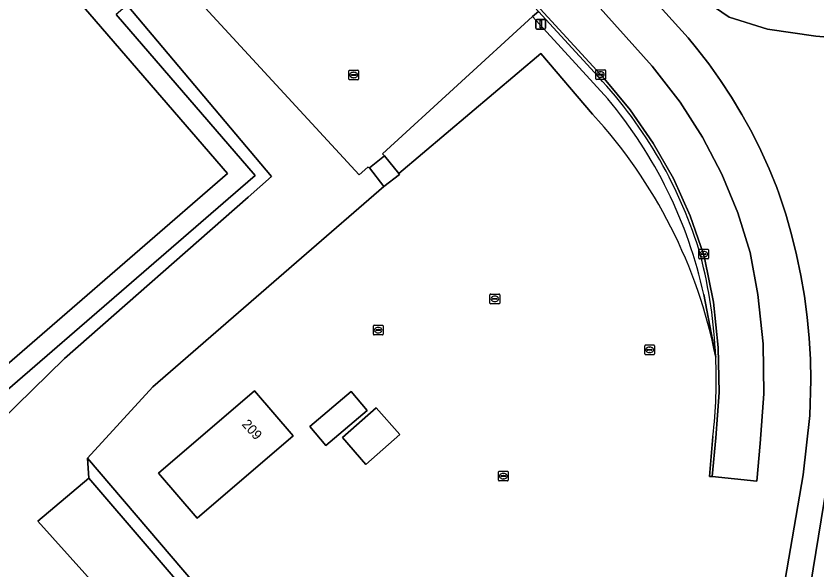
# Model space of a CAD drawing. Extents: x 156061 to 157804, y 383437 to 385640.
# Drawn here: x 157609.8 to 157692.3, y 383598 to 383655.1 of the extents above; entities that cross this region are included whole.
import ezdxf

# ---------------------------------------------------------------- set-up
doc = ezdxf.new("R2010")
doc.units = 0
for name, color, linetype in [('IMGEO_Erf', 7, 'Continuous'), ('IMGEO_Fietspad_gesloten', 7, 'Continuous'), ('IMGEO_Grasland_overig', 7, 'Continuous'), ('IMGEO_Groenvoorziening', 7, 'Continuous'), ('IMGEO_Hek', 7, 'Continuous'), ('IMGEO_Kolk', 7, 'Continuous'), ('IMGEO_Lichtmast', 7, 'Continuous'), ('IMGEO_Meer_plas_ven_vijver', 7, 'Continuous'), ('IMGEO_Oever', 7, 'Continuous'), ('IMGEO_Pand', 7, 'Continuous'), ('IMGEO_Pand_nummerreeks', 7, 'Continuous'), ('IMGEO_Rijbaan_lokaal_gesloten', 7, 'Continuous'), ('IMGEO_Rijbaan_lokaal_open', 7, 'Continuous'), ('IMGEO_Voetpad_gesloten', 7, 'Continuous')]:
    doc.layers.add(name, color=color, linetype=linetype)

msp = doc.modelspace()

# ---------------------------------------------------------------- linework, layer by layer
at = {"layer": 'IMGEO_Erf'}
for points in [[(157663.038, 383655.013), (157663.63, 383655.554), (157652.735, 383667.414), (157649.055, 383671.421), (157642.073, 383679.016), (157636.298, 383685.833), (157635.64, 383685.18), (157622.846, 383673.301), (157622.498, 383673.653), (157617.28, 383668.944), (157624.23, 383661.417), (157624.003, 383661.197), (157625.333, 383659.711), (157625.613, 383659.933), (157645.162, 383638.719), (157646.075, 383639.53), (157646.224, 383639.429), (157647.765, 383640.669), (157647.565, 383640.888)], [(157628.488, 383603.368), (157624.511, 383607.993), (157634.384, 383616.48), (157638.361, 383611.855)], [(157641.73, 383610.838), (157640.071, 383612.794), (157644.334, 383616.41), (157645.994, 383614.453)], [(157645.865, 383608.915), (157643.438, 383611.664), (157646.918, 383614.736), (157649.345, 383611.987)]]:
    msp.add_lwpolyline(points, close=True, dxfattribs=at)
for points in [[(157592.743, 383683.81), (157631.604, 383638.864), (157604.478, 383615.391), (157603.332, 383614.398), (157595.061, 383607.241), (157596.405, 383605.765), (157632.931, 383637.35), (157634.437, 383638.653), (157620.132, 383655.218)], [(157684.771, 383572.107), (157690.917, 383607.847), (157691.599, 383613.955), (157691.7, 383617.579), (157691.654, 383619.746), (157691.528, 383621.909), (157691.322, 383624.067), (157691.036, 383626.215), (157690.672, 383628.351), (157690.228, 383630.473), (157689.707, 383632.577), (157689.109, 383634.66), (157688.434, 383636.719), (157688.181, 383637.431), (157687.395, 383639.355), (157686.535, 383641.247), (157685.604, 383643.105), (157684.601, 383644.926), (157683.529, 383646.707), (157682.39, 383648.445), (157681.184, 383650.138), (157679.914, 383651.783), (157679.054, 383652.828), (157668.815, 383664.162)], [(157668.795, 383657.275), (157675.344, 383649.915), (157675.598, 383649.618), (157678.228, 383646.221), (157680.544, 383642.603), (157682.528, 383638.793), (157684.163, 383634.821), (157685.437, 383630.719), (157686.252, 383626.409), (157686.782, 383621.311), (157686.856, 383616.186), (157686.471, 383611.075), (157686.145, 383607.174), (157681.542, 383607.66), (157681.251, 383607.669), (157681.612, 383611.77)], [(157669.22, 383644.961), (157663.882, 383651.218), (157649.251, 383638.856), (157649.329, 383638.753), (157647.699, 383637.528), (157639.22, 383630.176), (157623.911, 383616.901), (157617.189, 383609.565), (157665.287, 383553.229)]]:
    msp.add_lwpolyline(points, dxfattribs=at)
for centre, radius, start, end in [((157631.14, 383609.93), 51.742, 11.18031, 42.61163), ((157630.359, 383617.673), 51.592, 353.42979, 2.54375)]:
    msp.add_arc(centre, radius, start, end, dxfattribs=at)
at = {"layer": 'IMGEO_Fietspad_gesloten'}
msp.add_lwpolyline([(157677.351, 383659.207), (157680.92, 383656.58), (157683.3, 383654.951), (157687.249, 383653.73), (157692.2, 383653.007), (157695.992, 383652.677), (157702.093, 383652.679)], dxfattribs=at)
at = {"layer": 'IMGEO_Grasland_overig'}
msp.add_lwpolyline([(157665.287, 383553.229), (157617.189, 383609.565), (157617.318, 383607.508), (157666.014, 383550.759)], dxfattribs=at)
at = {"layer": 'IMGEO_Groenvoorziening'}
for points in [[(157668.815, 383664.162), (157679.054, 383652.828), (157679.914, 383651.783), (157681.184, 383650.138), (157682.39, 383648.445), (157683.529, 383646.707), (157684.601, 383644.926), (157685.604, 383643.105), (157686.535, 383641.247), (157687.395, 383639.355), (157688.181, 383637.431), (157688.434, 383636.719), (157689.109, 383634.66), (157689.707, 383632.577), (157690.228, 383630.473), (157690.672, 383628.351), (157691.036, 383626.215), (157691.322, 383624.067), (157691.528, 383621.909), (157691.654, 383619.746), (157691.7, 383617.579), (157691.599, 383613.955), (157690.917, 383607.847), (157684.771, 383572.107)], [(157702.093, 383652.679), (157695.992, 383652.677), (157692.2, 383653.007), (157687.249, 383653.73), (157683.3, 383654.951), (157680.92, 383656.58), (157677.351, 383659.207)], [(157669.795, 383648.842), (157663.63, 383655.554), (157663.038, 383655.013), (157670.77, 383646.55)], [(157670.77, 383646.55), (157663.038, 383655.013), (157647.565, 383640.888), (157647.765, 383640.669), (157649.251, 383638.856), (157663.882, 383651.218), (157669.22, 383644.961)], [(157681.9, 383619.963), (157680.668, 383626.41)], [(157680.668, 383626.41), (157681.9, 383619.963)], [(157689.63, 383522.84), (157689.875, 383524.141), (157686.145, 383524.416), (157685.129, 383524.064), (157683.797, 383523.916), (157682.677, 383524.301), (157681.923, 383525.009), (157681.65, 383525.865), (157681.656, 383527.801), (157682.768, 383535.446), (157685.102, 383556.062), (157686.447, 383563.344), (157687.967, 383573.008), (157691.921, 383598.148), (157695.746, 383621.484)], [(157666.014, 383550.759), (157617.318, 383607.508), (157612.047, 383603.052), (157630.214, 383582.846)]]:
    msp.add_lwpolyline(points, dxfattribs=at)
for points in [[(157617.318, 383607.508), (157617.189, 383609.565), (157623.911, 383616.901), (157639.22, 383630.176), (157647.699, 383637.528), (157646.224, 383639.429), (157646.075, 383639.53), (157645.162, 383638.719), (157625.613, 383659.933), (157625.333, 383659.711), (157621.256, 383656.181), (157636.145, 383638.565), (157633.728, 383636.44), (157614.798, 383619.797), (157598.3, 383603.675), (157604.166, 383597.049), (157613.461, 383586.57), (157620.486, 383578.692), (157622.825, 383576.06), (157630.214, 383582.846), (157612.047, 383603.052)], [(157596.405, 383605.765), (157598.042, 383603.967), (157598.3, 383603.675), (157614.798, 383619.797), (157633.728, 383636.44), (157636.145, 383638.565), (157621.256, 383656.181), (157620.132, 383655.218), (157634.437, 383638.653), (157632.931, 383637.35)]]:
    msp.add_lwpolyline(points, close=True, dxfattribs=at)
for centre, radius, start, end in [((157635.883, 383617.185), 46.391, 16.60587, 43.03067), ((157634.734, 383616.337), 47.026, 12.36822, 39.97631), ((157634.734, 383616.337), 47.026, 12.36822, 39.97631), ((157631.14, 383609.93), 51.742, 11.18031, 42.61163), ((157630.586, 383617.681), 51.364, 2.54655, 14.38663)]:
    msp.add_arc(centre, radius, start, end, dxfattribs=at)
at = {"layer": 'IMGEO_Hek'}
for points in [[(157679.054, 383652.828), (157668.815, 383664.162), (157667.614, 383665.197)], [(157688.181, 383637.431), (157687.395, 383639.355), (157686.535, 383641.247), (157685.604, 383643.105), (157684.601, 383644.926), (157683.529, 383646.707), (157682.39, 383648.445), (157681.184, 383650.138), (157679.914, 383651.783), (157679.054, 383652.828)], [(157691.7, 383617.579), (157691.654, 383619.746), (157691.528, 383621.909), (157691.322, 383624.067), (157691.036, 383626.215), (157690.672, 383628.351), (157690.228, 383630.473), (157689.707, 383632.577), (157689.109, 383634.66), (157688.434, 383636.719), (157688.181, 383637.431)], [(157690.917, 383607.847), (157691.599, 383613.955), (157691.7, 383617.579)], [(157684.771, 383572.107), (157690.917, 383607.847)]]:
    msp.add_lwpolyline(points, dxfattribs=at)
at = {"layer": 'IMGEO_Kolk'}
for p, q in [((157644.177, 383649.505), (157645.029, 383649.505)), ((157669.534, 383648.618), (157669.534, 383649.47)), ((157669.609, 383649.544), (157670.461, 383649.544)), ((157670.535, 383649.47), (157670.535, 383648.618)), ((157644.102, 383648.579), (157644.102, 383649.431)), ((157644.361, 383648.999), (157644.361, 383649.011)), ((157644.799, 383648.962), (157644.401, 383648.962)), ((157644.404, 383649.048), (157644.802, 383649.048)), ((157644.613, 383648.725), (157644.588, 383648.725)), ((157644.59, 383649.285), (157644.615, 383649.285)), ((157644.845, 383649.011), (157644.845, 383648.999)), ((157645.103, 383649.431), (157645.103, 383648.579)), ((157669.793, 383649.038), (157669.793, 383649.05)), ((157670.231, 383649.001), (157669.833, 383649.001)), ((157669.836, 383649.087), (157670.234, 383649.087)), ((157670.045, 383648.764), (157670.02, 383648.764)), ((157670.022, 383649.324), (157670.047, 383649.324)), ((157670.277, 383649.05), (157670.277, 383649.038)), ((157645.029, 383648.505), (157644.177, 383648.505)), ((157670.461, 383648.544), (157669.609, 383648.544)), ((157680.154, 383630.134), (157680.154, 383630.986)), ((157680.229, 383631.06), (157681.081, 383631.06)), ((157680.413, 383630.554), (157680.413, 383630.566)), ((157680.851, 383630.517), (157680.453, 383630.517)), ((157680.456, 383630.603), (157680.854, 383630.603)), ((157680.642, 383630.84), (157680.667, 383630.84)), ((157680.897, 383630.566), (157680.897, 383630.554)), ((157681.155, 383630.986), (157681.155, 383630.134)), ((157681.081, 383630.06), (157680.229, 383630.06)), ((157680.665, 383630.28), (157680.64, 383630.28)), ((157658.644, 383625.524), (157658.644, 383626.376)), ((157658.719, 383626.45), (157659.571, 383626.45)), ((157659.645, 383626.376), (157659.645, 383625.524)), ((157658.903, 383625.944), (157658.903, 383625.956)), ((157659.341, 383625.907), (157658.943, 383625.907)), ((157658.946, 383625.993), (157659.344, 383625.993)), ((157659.155, 383625.67), (157659.13, 383625.67)), ((157659.132, 383626.23), (157659.157, 383626.23)), ((157659.387, 383625.956), (157659.387, 383625.944)), ((157659.571, 383625.45), (157658.719, 383625.45)), ((157646.629, 383622.314), (157646.629, 383623.166)), ((157646.704, 383623.24), (157647.556, 383623.24)), ((157647.63, 383623.166), (157647.63, 383622.314)), ((157647.556, 383622.24), (157646.704, 383622.24)), ((157646.888, 383622.734), (157646.888, 383622.746)), ((157647.326, 383622.697), (157646.928, 383622.697)), ((157646.931, 383622.783), (157647.329, 383622.783)), ((157647.14, 383622.46), (157647.115, 383622.46)), ((157647.117, 383623.02), (157647.142, 383623.02)), ((157647.372, 383622.746), (157647.372, 383622.734)), ((157674.591, 383620.278), (157674.591, 383621.13)), ((157674.666, 383621.204), (157675.518, 383621.204)), ((157674.85, 383620.698), (157674.85, 383620.71)), ((157675.288, 383620.661), (157674.89, 383620.661)), ((157674.893, 383620.747), (157675.291, 383620.747)), ((157675.079, 383620.984), (157675.104, 383620.984)), ((157675.334, 383620.71), (157675.334, 383620.698)), ((157675.592, 383621.13), (157675.592, 383620.278)), ((157675.518, 383620.204), (157674.666, 383620.204)), ((157675.102, 383620.424), (157675.077, 383620.424)), ((157659.594, 383608.207), (157660.446, 383608.207)), ((157659.519, 383607.281), (157659.519, 383608.133)), ((157659.778, 383607.701), (157659.778, 383607.713)), ((157660.216, 383607.664), (157659.818, 383607.664)), ((157659.821, 383607.75), (157660.219, 383607.75)), ((157660.03, 383607.427), (157660.005, 383607.427)), ((157660.007, 383607.987), (157660.032, 383607.987)), ((157660.262, 383607.713), (157660.262, 383607.701)), ((157660.52, 383608.133), (157660.52, 383607.281)), ((157660.446, 383607.207), (157659.594, 383607.207))]:
    msp.add_line(p, q, dxfattribs=at)
for points in [[(157644.177, 383649.505), (157645.029, 383649.505)], [(157669.534, 383648.618), (157669.534, 383649.47)], [(157669.609, 383649.544), (157670.461, 383649.544)], [(157670.535, 383649.47), (157670.535, 383648.618)], [(157644.102, 383648.579), (157644.102, 383649.431)], [(157645.103, 383649.431), (157645.103, 383648.579)], [(157645.029, 383648.505), (157644.177, 383648.505)], [(157670.461, 383648.544), (157669.609, 383648.544)], [(157680.154, 383630.134), (157680.154, 383630.986)], [(157680.229, 383631.06), (157681.081, 383631.06)], [(157681.155, 383630.986), (157681.155, 383630.134)], [(157681.081, 383630.06), (157680.229, 383630.06)], [(157658.644, 383625.524), (157658.644, 383626.376)], [(157658.719, 383626.45), (157659.571, 383626.45)], [(157659.645, 383626.376), (157659.645, 383625.524)], [(157659.571, 383625.45), (157658.719, 383625.45)], [(157646.629, 383622.314), (157646.629, 383623.166)], [(157646.704, 383623.24), (157647.556, 383623.24)], [(157647.63, 383623.166), (157647.63, 383622.314)], [(157647.556, 383622.24), (157646.704, 383622.24)], [(157674.591, 383620.278), (157674.591, 383621.13)], [(157674.666, 383621.204), (157675.518, 383621.204)], [(157675.592, 383621.13), (157675.592, 383620.278)], [(157675.518, 383620.204), (157674.666, 383620.204)], [(157659.594, 383608.207), (157660.446, 383608.207)], [(157659.519, 383607.281), (157659.519, 383608.133)], [(157660.52, 383608.133), (157660.52, 383607.281)], [(157660.446, 383607.207), (157659.594, 383607.207)]]:
    msp.add_lwpolyline(points, dxfattribs=at)
for centre, radius, start, end in [((157644.179, 383649.429), 0.0765, 91.55205, 178.44795), ((157644.179, 383649.429), 0.0765, 91.55205, 178.44795), ((157645.027, 383649.429), 0.0765, 1.55205, 88.44795), ((157645.027, 383649.429), 0.0765, 1.55205, 88.44795), ((157669.611, 383649.468), 0.0765, 91.55205, 178.44795), ((157669.611, 383649.468), 0.0765, 91.55205, 178.44795), ((157670.459, 383649.468), 0.0765, 1.55205, 88.44795), ((157670.459, 383649.468), 0.0765, 1.55205, 88.44795), ((157644.401, 383649.008), 0.0403, 85.87752, 175.75265), ((157644.398, 383648.998), 0.0366, 178.93798, 274.71019), ((157644.802, 383649.005), 0.043, 264.86636, 352.45326), ((157644.806, 383649.01), 0.0386, 1.73085, 96.63898), ((157669.611, 383648.62), 0.0765, 181.55205, 268.44795), ((157669.611, 383648.62), 0.0765, 181.55205, 268.44795), ((157669.833, 383649.047), 0.0403, 85.87752, 175.75265), ((157669.83, 383649.037), 0.0366, 178.93798, 274.71019), ((157670.234, 383649.044), 0.043, 264.86636, 352.45326), ((157670.238, 383649.049), 0.0386, 1.73085, 96.63898), ((157670.459, 383648.62), 0.0765, 271.55205, 358.44795), ((157670.459, 383648.62), 0.0765, 271.55205, 358.44795), ((157644.179, 383648.581), 0.0765, 181.55205, 268.44795), ((157644.179, 383648.581), 0.0765, 181.55205, 268.44795), ((157645.027, 383648.581), 0.0765, 271.55205, 358.44795), ((157645.027, 383648.581), 0.0765, 271.55205, 358.44795), ((157680.231, 383630.984), 0.0765, 91.55205, 178.44795), ((157680.231, 383630.984), 0.0765, 91.55205, 178.44795), ((157680.453, 383630.563), 0.0403, 85.87752, 175.75265), ((157680.45, 383630.553), 0.0366, 178.93798, 274.71019), ((157680.854, 383630.56), 0.043, 264.86636, 352.45326), ((157680.858, 383630.565), 0.0386, 1.73085, 96.63898), ((157681.079, 383630.984), 0.0765, 1.55205, 88.44795), ((157681.079, 383630.984), 0.0765, 1.55205, 88.44795), ((157680.231, 383630.136), 0.0765, 181.55205, 268.44795), ((157680.231, 383630.136), 0.0765, 181.55205, 268.44795), ((157681.079, 383630.136), 0.0765, 271.55205, 358.44795), ((157681.079, 383630.136), 0.0765, 271.55205, 358.44795), ((157658.721, 383626.374), 0.0765, 91.55205, 178.44795), ((157658.721, 383626.374), 0.0765, 91.55205, 178.44795), ((157659.569, 383626.374), 0.0765, 1.55205, 88.44795), ((157659.569, 383626.374), 0.0765, 1.55205, 88.44795), ((157658.721, 383625.526), 0.0765, 181.55205, 268.44795), ((157658.721, 383625.526), 0.0765, 181.55205, 268.44795), ((157658.943, 383625.953), 0.0403, 85.87752, 175.75265), ((157658.94, 383625.943), 0.0366, 178.93798, 274.71019), ((157659.344, 383625.95), 0.043, 264.86636, 352.45326), ((157659.348, 383625.955), 0.0386, 1.73085, 96.63898), ((157659.569, 383625.526), 0.0765, 271.55205, 358.44795), ((157659.569, 383625.526), 0.0765, 271.55205, 358.44795), ((157646.706, 383623.164), 0.0765, 91.55205, 178.44795), ((157646.706, 383623.164), 0.0765, 91.55205, 178.44795), ((157647.554, 383623.164), 0.0765, 1.55205, 88.44795), ((157647.554, 383623.164), 0.0765, 1.55205, 88.44795), ((157646.706, 383622.316), 0.0765, 181.55205, 268.44795), ((157646.706, 383622.316), 0.0765, 181.55205, 268.44795), ((157646.928, 383622.743), 0.0403, 85.87752, 175.75265), ((157646.925, 383622.733), 0.0366, 178.93798, 274.71019), ((157647.329, 383622.74), 0.043, 264.86636, 352.45326), ((157647.333, 383622.745), 0.0386, 1.73085, 96.63898), ((157647.554, 383622.316), 0.0765, 271.55205, 358.44795), ((157647.554, 383622.316), 0.0765, 271.55205, 358.44795), ((157674.668, 383621.128), 0.0765, 91.55205, 178.44795), ((157674.668, 383621.128), 0.0765, 91.55205, 178.44795), ((157674.89, 383620.707), 0.0403, 85.87752, 175.75265), ((157674.887, 383620.697), 0.0366, 178.93798, 274.71019), ((157675.291, 383620.704), 0.043, 264.86636, 352.45326), ((157675.295, 383620.709), 0.0386, 1.73085, 96.63898), ((157675.516, 383621.128), 0.0765, 1.55205, 88.44795), ((157675.516, 383621.128), 0.0765, 1.55205, 88.44795), ((157674.668, 383620.28), 0.0765, 181.55205, 268.44795), ((157674.668, 383620.28), 0.0765, 181.55205, 268.44795), ((157675.516, 383620.28), 0.0765, 271.55205, 358.44795), ((157675.516, 383620.28), 0.0765, 271.55205, 358.44795), ((157659.596, 383608.131), 0.0765, 91.55205, 178.44795), ((157659.596, 383608.131), 0.0765, 91.55205, 178.44795), ((157660.444, 383608.131), 0.0765, 1.55205, 88.44795), ((157660.444, 383608.131), 0.0765, 1.55205, 88.44795), ((157659.818, 383607.71), 0.0403, 85.87752, 175.75265), ((157659.815, 383607.7), 0.0366, 178.93798, 274.71019), ((157660.219, 383607.707), 0.043, 264.86636, 352.45326), ((157660.223, 383607.712), 0.0386, 1.73085, 96.63898), ((157659.596, 383607.283), 0.0765, 181.55205, 268.44795), ((157659.596, 383607.283), 0.0765, 181.55205, 268.44795), ((157660.444, 383607.283), 0.0765, 271.55205, 358.44795), ((157660.444, 383607.283), 0.0765, 271.55205, 358.44795)]:
    msp.add_arc(centre, radius, start, end, dxfattribs=at)
for centre, major_axis, ratio, start_param, end_param in [((157644.589, 383649.005), (-0.387, 0.002), 0.722429, 4.712389, 7.853982), ((157644.614, 383649.005), (-0.39, 0.002), 0.717154, 1.570796, 4.712389), ((157670.021, 383649.044), (-0.387, 0.002), 0.722429, 4.712389, 7.853982), ((157670.046, 383649.044), (-0.39, 0.002), 0.717154, 1.570796, 4.712389), ((157680.641, 383630.56), (-0.387, 0.002), 0.722429, 4.712389, 7.853982), ((157680.666, 383630.56), (-0.39, 0.002), 0.717154, 1.570796, 4.712389), ((157659.131, 383625.95), (-0.387, 0.002), 0.722429, 4.712389, 7.853982), ((157659.156, 383625.95), (-0.39, 0.002), 0.717154, 1.570796, 4.712389), ((157647.116, 383622.74), (-0.387, 0.002), 0.722429, 4.712389, 7.853982), ((157647.141, 383622.74), (-0.39, 0.002), 0.717154, 1.570796, 4.712389), ((157675.078, 383620.704), (-0.387, 0.002), 0.722429, 4.712389, 7.853982), ((157675.103, 383620.704), (-0.39, 0.002), 0.717154, 1.570796, 4.712389), ((157660.006, 383607.707), (-0.387, 0.002), 0.722429, 4.712389, 7.853982), ((157660.031, 383607.707), (-0.39, 0.002), 0.717154, 1.570796, 4.712389)]:
    msp.add_ellipse(centre, major_axis=major_axis, ratio=ratio, start_param=start_param, end_param=end_param, dxfattribs=at)
at = {"layer": 'IMGEO_Lichtmast'}
for p, q in [((157663.377, 383653.828), (157663.377, 383654.628)), ((157663.377, 383654.628), (157663.377, 383653.828)), ((157663.477, 383654.728), (157664.267, 383654.728)), ((157664.267, 383654.728), (157663.477, 383654.728)), ((157664.367, 383654.628), (157664.367, 383653.828)), ((157664.367, 383653.828), (157664.367, 383654.628)), ((157664.267, 383653.728), (157663.477, 383653.728)), ((157663.477, 383653.728), (157664.267, 383653.728))]:
    msp.add_line(p, q, dxfattribs=at)
msp.add_lwpolyline([(157663.797, 383654.603), (157663.947, 383654.603), (157663.947, 383653.853), (157663.797, 383653.853), (157663.797, 383654.603)], dxfattribs=at)
for centre, start, end in [((157663.477, 383654.628), 90, 180), ((157663.477, 383654.628), 90, 180), ((157664.267, 383654.628), 0, 90), ((157664.267, 383654.628), 360, 90), ((157663.477, 383653.828), 180, 270), ((157663.477, 383653.828), 180, 270), ((157664.267, 383653.828), 270, 0), ((157664.267, 383653.828), 270, 0)]:
    msp.add_arc(centre, 0.1, start, end, dxfattribs=at)
at = {"layer": 'IMGEO_Meer_plas_ven_vijver'}
msp.add_lwpolyline([(157536.954, 383682.315), (157537.085, 383682.162), (157532.924, 383678.599), (157532.815, 383678.725), (157532.494, 383678.447), (157553.514, 383655.202), (157554.504, 383654.072), (157594.504, 383606.759), (157594.683, 383606.913), (157595.061, 383607.241), (157603.332, 383614.398), (157604.478, 383615.391), (157631.604, 383638.864), (157592.743, 383683.81), (157592.085, 383684.583), (157589.969, 383686.975), (157584.203, 383693.494), (157593.316, 383701.326), (157589.181, 383706.103), (157580.09, 383698.235), (157574.434, 383704.864), (157569.551, 383710.587), (157546.586, 383690.669), (157545.842, 383690.024)], close=True, dxfattribs=at)
at = {"layer": 'IMGEO_Oever'}
msp.add_lwpolyline([(157695.746, 383621.484), (157691.921, 383598.148), (157687.967, 383573.008), (157686.447, 383563.344), (157685.102, 383556.062), (157682.768, 383535.446), (157681.656, 383527.801), (157681.65, 383525.865), (157681.923, 383525.009), (157682.677, 383524.301), (157683.797, 383523.916), (157685.129, 383524.064), (157686.145, 383524.416), (157686.803, 383525.078), (157687.107, 383526.217), (157687.23, 383526.677), (157687.487, 383527.64), (157688.82, 383536.832), (157690.73, 383552.687), (157692.962, 383569.443)], dxfattribs=at)
at = {"layer": 'IMGEO_Pand'}
for points in [[(157628.488, 383603.368), (157638.361, 383611.855), (157634.384, 383616.48), (157624.511, 383607.993)], [(157645.994, 383614.453), (157644.334, 383616.41), (157640.071, 383612.794), (157641.73, 383610.838)], [(157649.345, 383611.987), (157646.918, 383614.736), (157643.438, 383611.664), (157645.865, 383608.915)]]:
    msp.add_lwpolyline(points, close=True, dxfattribs=at)
at = {"layer": 'IMGEO_Rijbaan_lokaal_gesloten'}
msp.add_lwpolyline([(157640.558, 383681.144), (157670.038, 383649.042), (157670.403, 383648.646), (157673.087, 383645.425), (157675.471, 383641.977), (157677.539, 383638.33), (157679.272, 383634.513), (157680.657, 383630.556), (157680.752, 383630.175), (157681.665, 383625.6), (157682.165, 383620.962), (157682.248, 383616.298), (157681.915, 383611.645), (157681.542, 383607.66), (157686.145, 383607.174), (157686.471, 383611.075), (157686.856, 383616.186), (157686.782, 383621.311), (157686.252, 383626.409), (157685.437, 383630.719), (157684.163, 383634.821), (157682.528, 383638.793), (157680.544, 383642.603), (157678.228, 383646.221), (157675.598, 383649.618), (157675.344, 383649.915), (157668.795, 383657.275)], dxfattribs=at)
at = {"layer": 'IMGEO_Rijbaan_lokaal_open'}
for points in [[(157681.612, 383611.77), (157681.251, 383607.669), (157681.542, 383607.66), (157681.915, 383611.645), (157682.248, 383616.298), (157682.165, 383620.962), (157681.665, 383625.6), (157680.752, 383630.175), (157680.657, 383630.556), (157679.272, 383634.513), (157677.539, 383638.33), (157675.471, 383641.977), (157673.087, 383645.425), (157670.403, 383648.646), (157670.038, 383649.042), (157640.558, 383681.144)], [(157663.63, 383655.554), (157669.795, 383648.842)]]:
    msp.add_lwpolyline(points, dxfattribs=at)
for centre, radius, start, end in [((157635.883, 383617.185), 46.391, 16.60587, 43.03067), ((157630.586, 383617.681), 51.364, 2.54655, 14.38663), ((157630.359, 383617.673), 51.592, 353.42979, 2.54375)]:
    msp.add_arc(centre, radius, start, end, dxfattribs=at)
at = {"layer": 'IMGEO_Voetpad_gesloten'}
msp.add_lwpolyline([(157647.765, 383640.669), (157646.224, 383639.429), (157647.699, 383637.528), (157649.329, 383638.753), (157649.251, 383638.856)], close=True, dxfattribs=at)

# ---------------------------------------------------------------- texts
at = {"layer": 'IMGEO_Pand_nummerreeks'}
msp.add_text('209', height=1, rotation=311.98721, dxfattribs=at).set_placement((157633.019, 383613))

doc.saveas('drawing.dxf')
